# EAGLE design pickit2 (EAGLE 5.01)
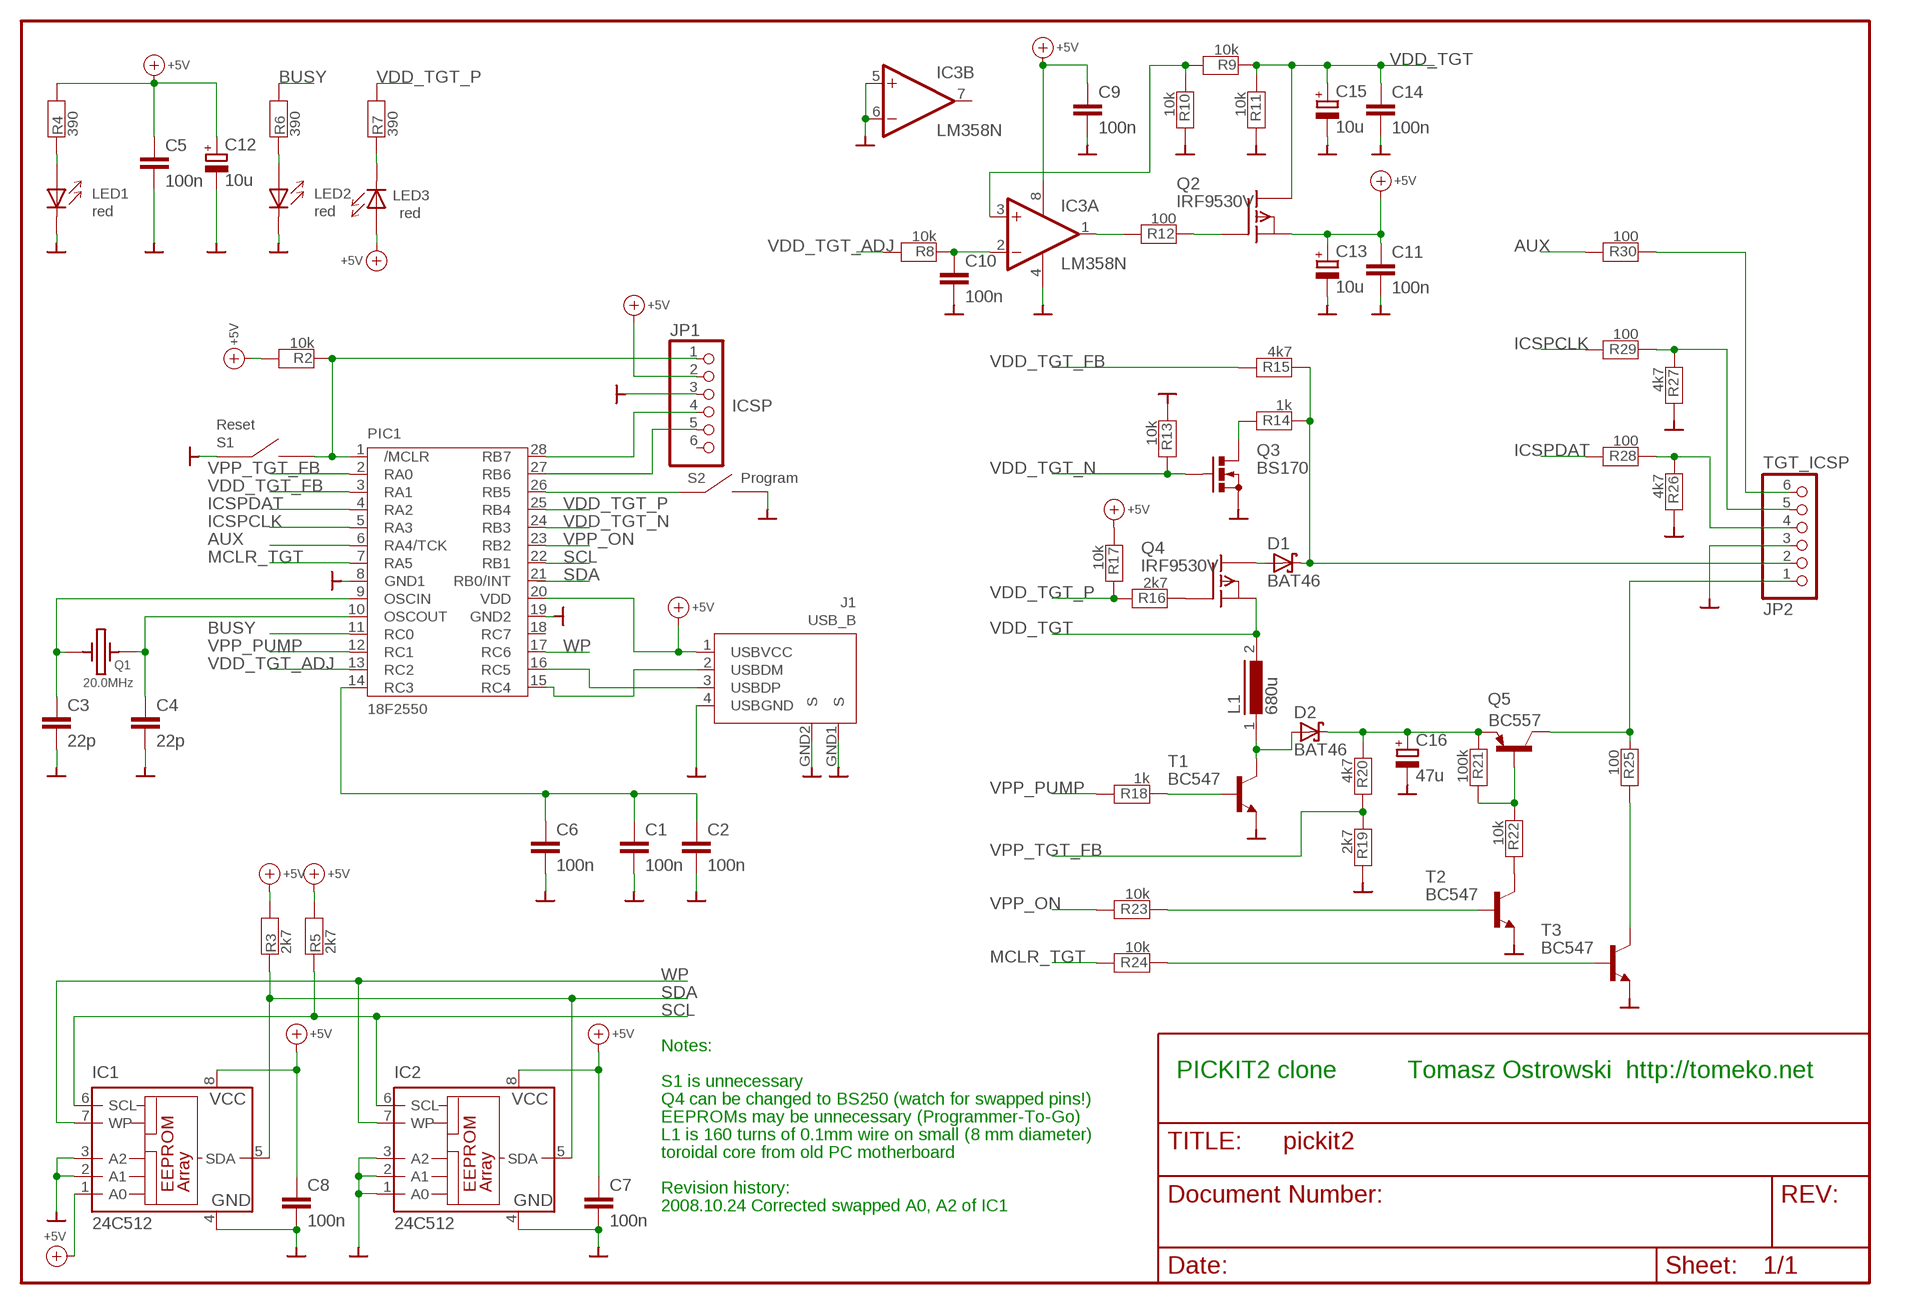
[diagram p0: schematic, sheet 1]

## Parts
C1  100n  C0805  [0805]
C2  100n  C0805  [0805]
C3  22p  C0805  [0805]
C4  22p  C0805  [0805]
C5  100n  C0805  [0805]
C6  100n  C0805  [0805]
C7  100n  C0805  [0805]
C8  100n  C0805  [0805]
C9  100n  C0805  [0805]
C10  100n  C0805  [0805]
C11  100n  C0805  [0805]
C12  10u  CPOL-EUE2,5-6E  [E2,5-6E]
C13  10u  CPOL-EUE2,5-6E  [E2,5-6E]
C14  100n  C0805  [0805]
C15  10u  CPOL-EUE2,5-6E  [E2,5-6E]
C16  47u  CPOL-EUE2,5-6E  [E2,5-6E]
D1  BAT46  BAT49  [DO41-10]
D2  BAT46  BAT49  [DO41-10]
IC1  24C512  24C04P  [DIL8]
IC2  24C512  24C04P  [DIL8]
IC3  LM358N  [DIL08]
J1  USB_B  [USB_B]
JP1  ICSP  PINHD-1X6  [1X06]
JP2  TGT_ICSP  PINHD-1X6  [1X06]
L1  680u  82114R  [82114R]
LED1  red  LED_5MM  [LED_5MM]
LED2  red  LED_5MM  [LED_5MM]
LED3  red  LED_5MM  [LED_5MM]
PIC1  18F2550  16C73  [DIL-28SB]
Q1  20.0MHz  QUARZ_STEH  [QUARZ_ST]
Q2  IRF9530V  [TO220V]
Q3  BS170  [SOT54E]
Q4  IRF9530V  [TO220V]
Q5  BC557  [TO92]
R2  10k  R_10MM  [RES04]
R3  2k7  R_10MM  [RES04]
R4  390  R_10MM@2  [RES04]
R5  2k7  R_10MM  [RES04]
R6  390  R_10MM@2  [RES04]
R7  390  R_10MM@2  [RES04]
R8  10k  R_10MM  [RES04]
R9  10k  R_10MM  [RES04]
R10  10k  R_10MM  [RES04]
R11  10k  R_10MM  [RES04]
R12  100  R_10MM  [RES04]
R13  10k  R_10MM  [RES04]
R14  1k  R_10MM  [RES04]
R15  4k7  R_10MM  [RES04]
R16  2k7  R_10MM  [RES04]
R17  10k  R_10MM  [RES04]
R18  1k  R_10MM  [RES04]
R19  2k7  R_10MM  [RES04]
R20  4k7  R_10MM  [RES04]
R21  100k  R_10MM  [RES04]
R22  10k  R_10MM  [RES04]
R23  10k  R_10MM  [RES04]
R24  10k  R_10MM  [RES04]
R25  100  R_10MM  [RES04]
R26  4k7  R_10MM  [RES04]
R27  4k7  R_10MM  [RES04]
R28  100  R_10MM  [RES04]
R29  100  R_10MM  [RES04]
R30  100  R_10MM  [RES04]
S1  Reset  MAUSTASTER  [MAUS]
S2  Program  MAUSTASTER  [MAUS]
T1  BC547  [TO92]
T2  BC547  [TO92]
T3  BC547  [TO92]

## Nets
+5V: C5.1 C7.1 C8.1 C9.1 C11.1 C12.+ C13.+ IC1.1(A0) IC1.8(VCC) IC2.8(VCC) IC3.8(P:V+) J1.1(USBVCC) JP1.2 LED3.A PIC1.20(VDD) Q2.3(S) R2.2 R3.2 R4.2 R5.2 R17.1
AUX: PIC1.6(RA4/TCK) R30.2
BUSY: PIC1.11(RC0) R6.2
GND: C1.2 C2.2 C3.2 C4.2 C5.2 C6.2 C7.2 C8.2 C9.2 C10.2 C11.2 C12.- C13.- C14.2 C15.- C16.- IC1.2(A1) IC1.3(A2) IC1.4(GND) IC2.1(A0) IC2.2(A1) IC2.3(A2) IC2.4(GND) IC3.4(P:V-) IC3.5(B:+IN) IC3.6(B:-IN) J1.4(USBGND) J1.GND1(S) J1.GND2(S) JP1.3 JP2.3 LED1.K LED2.K PIC1.8(GND1) PIC1.19(GND2) Q3.S R10.2 R11.2 R13.1 R19.2 R26.2 R27.2 S1.1 S1.1A S2.2 S2.2A T1.1(E) T2.1(E) T3.1(E)
ICSPCLK: PIC1.5(RA3) R29.2
ICSPDAT: PIC1.4(RA2) R28.2
J21: C1.1 C2.1 C6.1 PIC1.14(RC3)
MCLR_TGT: PIC1.7(RA5) R24.2
N$1: LED2.A R6.1
N$2: JP1.4 PIC1.28(RB7)
N$3: C3.1 PIC1.9(OSCIN) Q1.1
N$4: C4.1 PIC1.10(OSCOUT) Q1.2
N$5: JP1.5 PIC1.27(RB6)
N$6: LED3.K R7.1
N$7: LED1.A R4.1
N$8: J1.2(USBDM) PIC1.15(RC4)
N$9: J1.3(USBDP) PIC1.16(RC5)
N$10: PIC1.26(RB5) S2.1 S2.1A
N$11: C10.1 IC3.2(A:-IN) R8.1
N$12: IC3.3(A:+IN) R9.2 R10.1
N$14: Q3.D R14.2
N$15: D1.C JP2.2 R14.1 R15.1
N$16: JP1.1 PIC1.1(/MCLR) R2.1 S1.2 S1.2A
N$17: IC3.1(A:OUT) R12.2
N$18: Q2.1(G) R12.1
N$19: Q4.1(G) R16.1
N$20: D1.A Q4.2(D)
N$21: D2.A L1.1 T1.3(C)
N$22: R18.1 T1.2(B)
N$24: R24.1 T3.2(B)
N$25: C16.+ D2.C Q5.1(E) R20.1 R21.1
N$26: Q5.2(B) R21.2 R22.1
N$27: R22.2 T2.3(C)
N$28: R25.2 T3.3(C)
N$29: R23.1 T2.2(B)
N$30: JP2.1 Q5.3(C) R25.1
N$31: JP2.4 R26.1 R28.1
N$32: JP2.5 R27.1 R29.1
N$33: JP2.6 R30.1
SCL: IC1.6(SCL) IC2.6(SCL) PIC1.22(RB1) R5.1
SDA: IC1.5(SDA) IC2.5(SDA) PIC1.21(RB0/INT) R3.1
VDD_TGT: C14.1 C15.+ L1.2 Q2.2(D) Q4.3(S) R9.1 R11.1
VDD_TGT_ADJ: PIC1.13(RC2) R8.2
VDD_TGT_FB: PIC1.3(RA1) R15.2
VDD_TGT_N: PIC1.24(RB3) Q3.G R13.2
VDD_TGT_P: PIC1.25(RB4) R7.2 R16.2 R17.2
VPP_ON: PIC1.23(RB2) R23.2
VPP_PUMP: PIC1.12(RC1) R18.2
VPP_TGT_FB: PIC1.2(RA0) R19.1 R20.2
WP: IC1.7(WP) IC2.7(WP) PIC1.17(RC6)
Unconnected: IC3.7(B:OUT) JP1.6 PIC1.18(RC7)

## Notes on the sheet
- Notes:
- PICKIT2 clone | Tomasz Ostrowski  http://tomeko.net
- S1 is unnecessary
- Q4 can be changed to BS250 (watch for swapped pins!)
- EEPROMs may be unnecessary (Programmer-To-Go)
- L1 is 160 turns of 0.1mm wire on small (8 mm diameter)
- toroidal core from old PC motherboard
- Revision history:
- 2008.10.24 Corrected swapped A0, A2 of IC1

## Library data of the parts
C1-C11 C14 = capacitor-wima:C: CAPACITOR
C12 C13 C15 C16 = rcl:CPOL-EU: POLARIZED CAPACITOR, European symbol
D1 D2 = diode:BAT49: DIODE
IC1 IC2 = microchip:24C*: Serial EEPROM 1 K/2 K/4 K
IC3 = linear:LM358: OP AMP also LM158; LM258; LM2904 Source: http://cache.national.com/ds/LM/LM158.pdf
J1 = 8031bord:USB_B
JP1 JP2 = pinhead:PINHD-1X6: PIN HEADER
L1 = inductors:82114R: INDUCTOR
LED1-LED3 = holgnorm:LED_5MM
PIC1 = pic:16C73
Q1 = bts:QUARZ_STEH
Q2 Q4 = transistor-fet:IRF9530: P-Channel Enhancement MOSFET (HEXFET); -100V; -12A; 0,3Ohm
Q3 = transistor-small-signal:BS170: N-CHANNEL MOS FET
Q5 = transistor-pnp:BC557: PNP Transistor
R2 R3 R5 R8-R30 = holgnorm:R_10MM
R4 R6 R7 = holgnorm:R_10MM@2
S1 S2 = taster:MAUSTASTER
T1-T3 = transistor:BC547: NPN TRANSISTOR

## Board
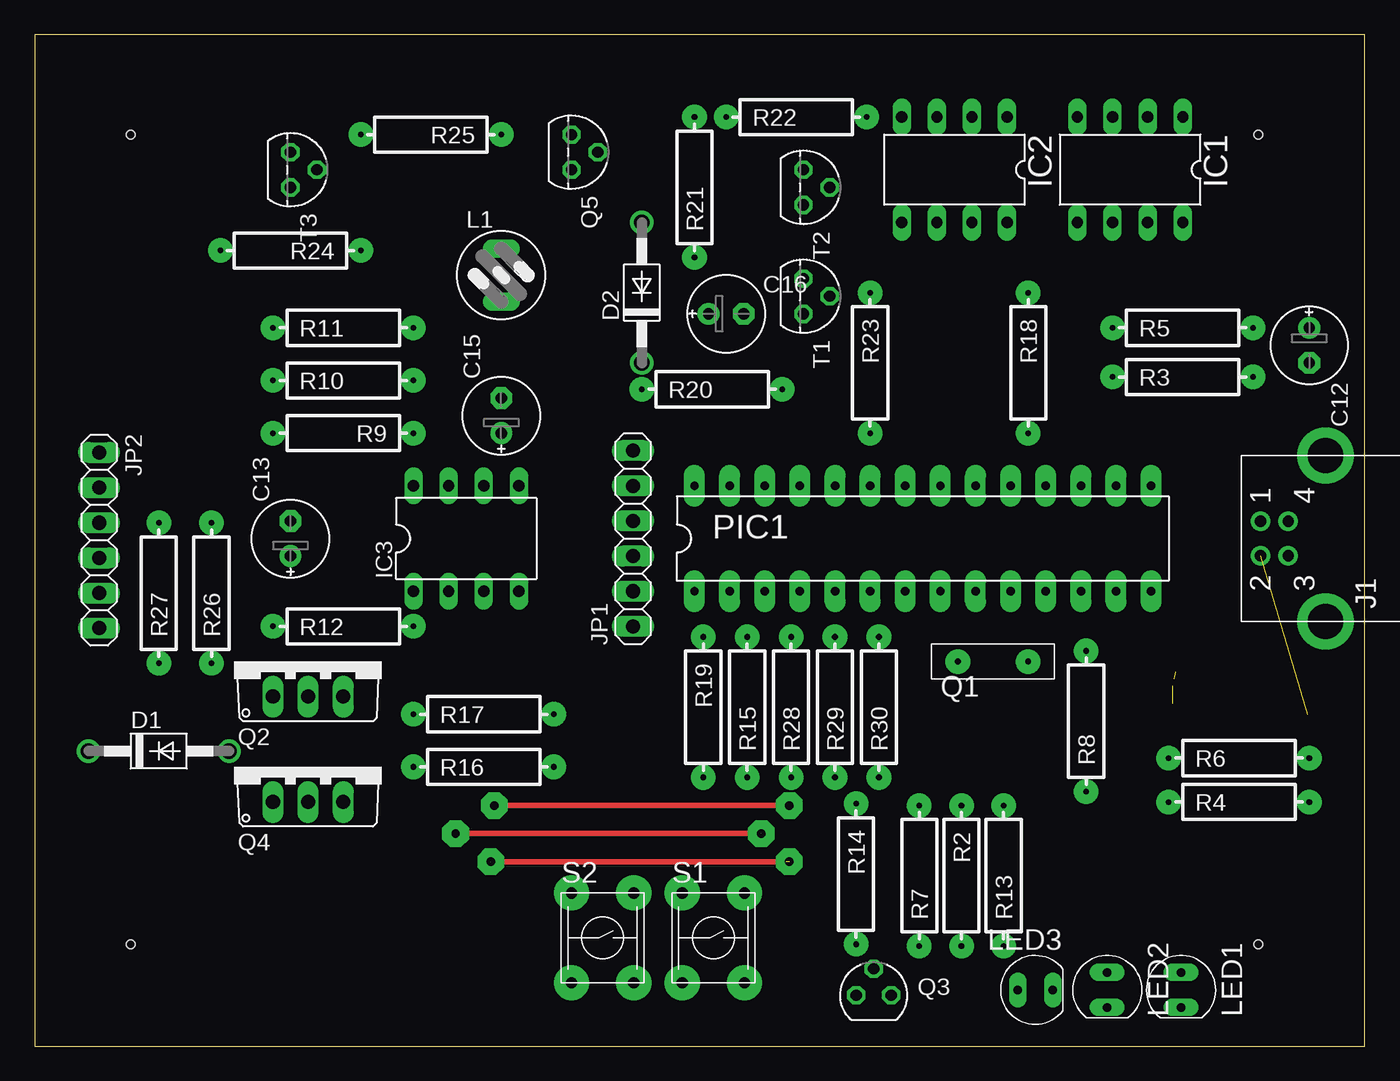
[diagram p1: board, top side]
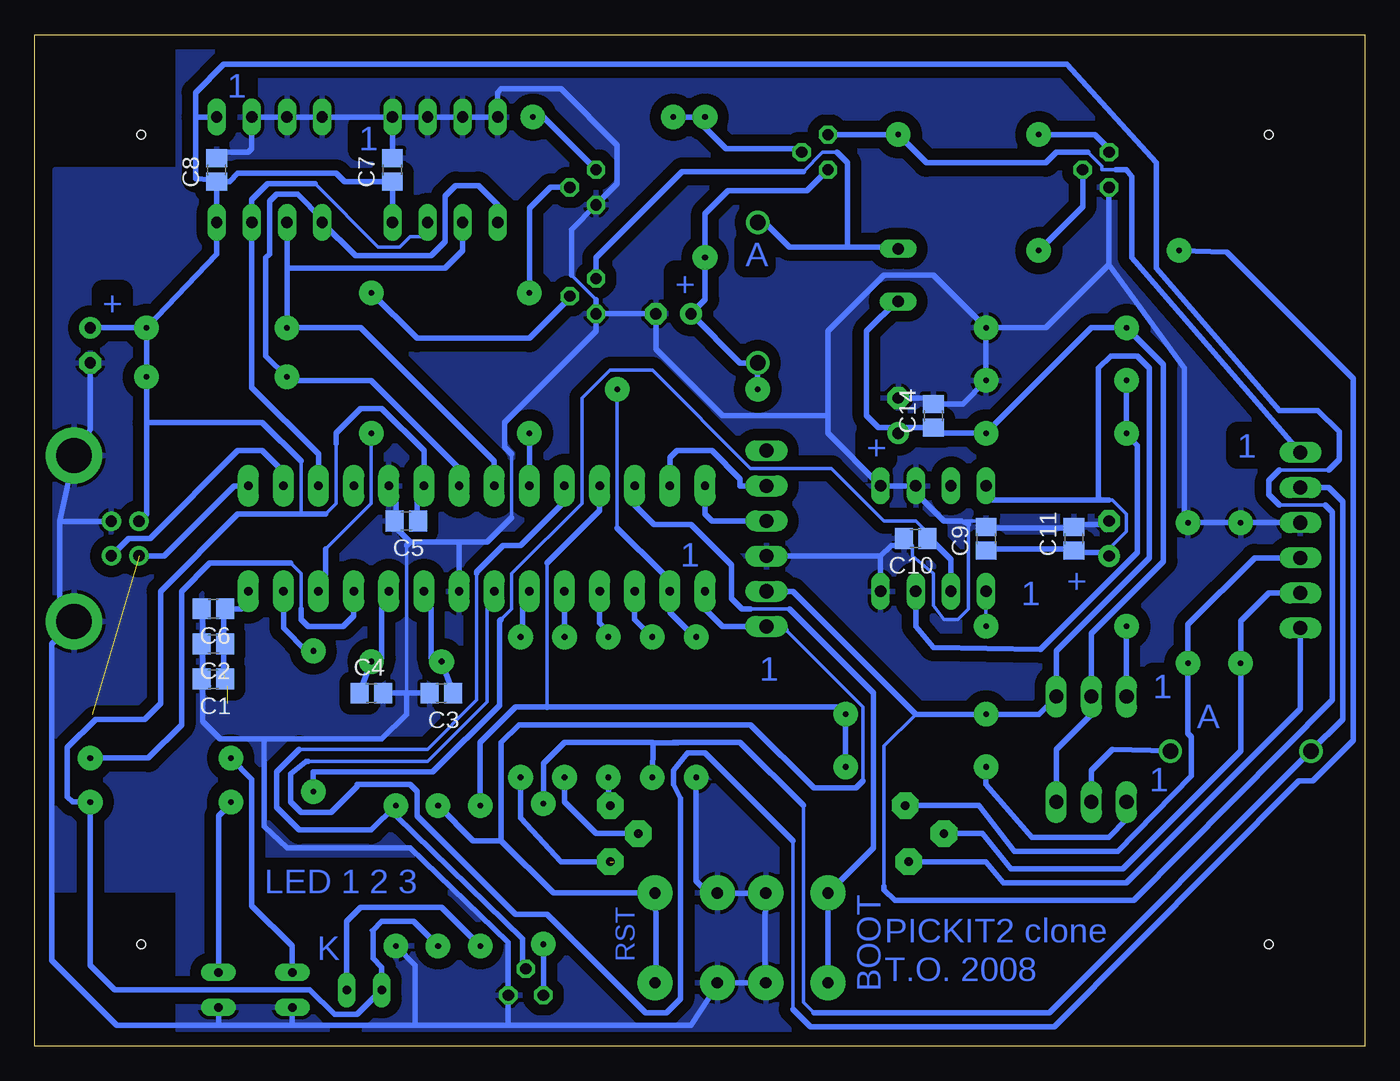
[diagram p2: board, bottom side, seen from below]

Size 96.19 x 73.14 mm. Coordinates in mm from the lower left corner, seen from the top.
Outline: 0,0 96.19,0 96.19,73.14 0,73.14 0,0
Copper layers (1*16): Top 0.035mm / dielectric 1.5mm / Bottom 0.035mm
Design rules "default *": minimum track width 10mil, minimum drill 24mil, track to track 12mil, track to pad 12mil, pad to pad 9mil, via to via 9mil, smd to smd 12mil, copper to edge 40mil, drill to drill 8mil, minimum pad ring 10mil, minimum via ring 8mil, stop-mask expansion 4mil, vias tented up to drill 0mil, thermal gap 10mil
Holes 0.6 mm at 6.95,7.36 6.95,65.91 88.48,65.91 88.48,7.36

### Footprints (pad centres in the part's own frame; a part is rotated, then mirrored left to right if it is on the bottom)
0805 = smd 1.3 x 1.5: 1 -0.85,0; 2 0.85,0
E2,5-6E = drill 0.813 pad 1.575 round: + -1.27,0 | drill 0.813 pad 1.575 octagon: - 1.27,0
DO41-10 = drill 1.118 round: A 5.08,0; C -5.08,0
DIL8 = drill 0.813 long: 1 -3.81,-3.81; 2 -1.27,-3.81; 3 1.27,-3.81; 4 3.81,-3.81; 5 3.81,3.81; 6 1.27,3.81; 7 -1.27,3.81; 8 -3.81,3.81
DIL08 = drill 0.813 long: 1 -3.81,-3.81; 2 -1.27,-3.81; 3 1.27,-3.81; 4 3.81,-3.81; 5 3.81,3.81; 6 1.27,3.81; 7 -1.27,3.81; 8 -3.81,3.81
USB_B = drill 0.813 pad 1.422 round: 1 1.25,2; 2 -1.25,2; 3 -1.25,0; 4 1.25,0 | drill 2.54 pad 4.064 round: GND1 6,-2.7; GND2 -6,-2.7
1X06 = drill 1.016 long: 1 -6.35,0; 2 -3.81,0; 3 -1.27,0; 4 1.27,0; 5 3.81,0; 6 6.35,0
82114R = drill 0.813 long: 1 0,1.905; 2 0,-1.905
LED_5MM = drill 0.61 pad 1.27 long: A -1.27,0; K 1.27,0
DIL-28SB = drill 0.61 pad 1.524 long: 1 0,0; 2 2.54,0; 3 5.08,0; 4 7.62,0; 5 10.16,0; 6 12.7,0; 7 15.24,0; 8 17.78,0; 9 20.32,0; 10 22.86,0; 11 25.4,0; 12 27.94,0; 13 30.48,0; 14 33.02,0; 15 33.02,7.62; 16 30.48,7.62; 17 27.94,7.62; 18 25.4,7.62; 19 22.86,7.62; 20 20.32,7.62; 21 17.78,7.62; 22 15.24,7.62; 23 12.7,7.62; 24 10.16,7.62; 25 7.62,7.62; 26 5.08,7.62; 27 2.54,7.62; 28 0,7.62
QUARZ_ST = drill 0.406 pad 1.778 round: 1 -2.54,0; 2 2.54,0
TO220V = drill 1.016 long: 1 -2.54,-2.54; 2 0,-2.54; 3 2.54,-2.54
SOT54E = drill 0.813 octagon: D -1.27,0; G 0,1.905; S 1.27,0
TO92 = drill 0.813 octagon: 1 1.27,0; 2 0,1.905; 3 -1.27,0
RES04 = drill 0.406 pad 1.778 round: 1 -5.08,0; 2 5.08,0
MAUS = drill 0.813 pad 2.54 round: 1 0,0; 1A 0,6.5; 2 4.5,0; 2A 4.5,6.5

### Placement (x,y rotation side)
C1  83.27,26.54 180 bottom
C2  83.27,29.08 180 bottom
C3  66.76,25.52 180 bottom
C4  71.84,25.52 0 bottom
C5  69.3,37.97 180 bottom
C6  83.27,31.62 180 bottom
C7  70.32,63.37 90 bottom
C8  83.02,63.37 90 bottom
C9  27.39,36.7 90 bottom
C10  32.47,36.7 180 bottom
C11  21.04,36.7 90 bottom
C12  92.16,50.67 270 top
C13  18.5,36.7 90 top
C14  31.2,45.59 90 bottom
C15  33.74,45.59 90 top
C16  50,52.95 0 top
D1  8.98,21.33 0 top
D2  43.9,54.48 90 top
IC1  79.21,63.37 180 top
IC2  66.51,63.37 180 top
IC3  31.2,36.7 0 top
J1  90.64,36.7 90 top
JP1  43.27,36.7 90 top
JP2  4.66,36.57 270 top
L1  33.74,55.75 0 top
LED1  82.89,4.06 270 top
LED2  77.56,4.06 270 top
LED3  72.35,4.06 0 top
PIC1  47.71,32.89 0 top
Q1  69.3,27.81 0 top
Q2  19.77,27.81 0 top
Q3  60.67,3.68 0 top
Q4  19.77,20.19 0 top
Q5  38.82,64.64 270 top
R2  67.02,12.31 270 top
R3  83.02,48.38 0 top
R4  87.08,17.65 0 top
R5  83.02,51.94 0 top
R6  87.08,20.82 0 top
R7  63.97,12.31 90 top
R8  76.03,23.49 90 top
R9  22.31,44.32 180 top
R10  22.31,48.13 0 top
R11  22.31,51.94 0 top
R12  22.31,30.35 0 top
R13  70.07,12.31 90 top
R14  59.4,12.44 270 top
R15  51.52,24.51 90 top
R16  32.47,20.19 0 top
R17  32.47,24 0 top
R18  71.84,49.4 270 top
R19  48.35,24.51 270 top
R20  48.98,47.49 0 top
R21  47.71,62.1 90 top
R22  55.08,67.18 0 top
R23  60.41,49.4 270 top
R24  18.5,57.53 180 top
R25  28.66,65.91 180 top
R26  12.79,32.76 90 top
R27  8.98,32.76 90 top
R28  54.7,24.51 90 top
R29  57.87,24.51 90 top
R30  61.05,24.51 90 top
S1  46.83,4.57 0 top
S2  38.82,4.57 0 top
T1  55.59,54.22 270 top
T2  55.59,62.1 270 top
T3  18.5,63.37 270 top

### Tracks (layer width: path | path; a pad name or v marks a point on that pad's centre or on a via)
+5V
  Bottom 0.254: 20.54,35.68 C11.1 21.55,35.94 | 26.89,35.94 C9.1 | 18.5,39.49 18.25,39.49 17.23,38.48 17.23,37.21 18.25,36.19 C13.+ | 68.54,38.48 C5.1 | 74.38,43.56 74.38,39.24 75.15,38.48 | 34.76,11.55 34.76,21.71 32.47,24 | 2.38,25.01 2.38,24.89 | 2.88,39.11 6.18,39.11 | 6.18,41.65 2.63,41.65 | C8.1 83.53,62.61 | 76.92,42.29 76.92,38.48 | 71.72,8.38 71.84,8.38
  Bottom 0.406: 20.54,35.68 19.27,35.68 C13.+ | 21.55,35.94 26.89,35.94 | 19.14,39.49 18.5,39.49 | 19.14,39.49 26.89,39.49 IC3.8 | C8.1 IC1.8 83.02,57.27 R5.2 | R5.2 C12.+ | 68.54,38.48 68.54,39.24 PIC1.20 68.03,43.05 71.08,46.1 72.61,46.1 74.38,44.32 74.38,43.56 | IC2.8 C7.1 73.79,62.52 74.38,63.11 81.5,63.11 82.09,62.52 C8.1 | 2.88,39.11 2.38,38.6 2.38,25.01 16.73,10.54 34,10.54 34.76,11.3 34.76,11.55 | 6.18,39.11 6.95,39.87 6.95,40.89 6.18,41.65 | 2.63,41.65 1.87,42.41 1.87,44.45 3.39,45.97 6.18,45.97 15.08,56.26 15.08,63.88 21.55,70.99 82.51,70.99 84.54,68.96 84.54,67.18 | R5.2 R3.2 88.1,45.08 | 88.1,45.08 88.1,38.48 88.63,37.95 J1.1 | 75.15,38.48 76.92,38.48 81.5,38.48 87.08,32.89 87.08,24.76 88.23,23.62 91.78,23.62 93.81,21.58 93.81,18.03 93.43,17.65 R4.2 92.16,5.84 90.39,4.06 76.29,4.06 74.51,2.28 72.86,2.28 LED3.A 70.95,4.06 71.08,4.19 71.08,5.71 71.72,6.34 71.72,8.38 71.08,9.01 68.8,9.01 R2.2 | 76.92,42.29 79.72,45.08 88.1,45.08 | 84.54,67.18 84.54,62.73 83.02,62.61 C8.1 | JP1.2 41.36,32.89 32.47,24 27.65,24 27.39,23.74 R17.1 23.58,24 Q2.3 22.31,28.57 15.58,35.3 15.58,49.02 16.47,49.91 18.38,49.91 19.27,49.02 19.27,39.62 19.14,39.49 | 84.54,67.18 IC1.1
AUX
  Bottom 0.254: R30.2 60.92,29.59
  Bottom 0.406: PIC1.6 60.92,31.62 60.92,29.59
BUSY
  Bottom 0.254: 76.92,31.62 76.92,34.16 77.69,34.92
  Bottom 0.406: 77.69,34.92 83.53,34.92 85.56,32.89 85.56,23.24 87.97,20.82 92.04,20.82 92.16,20.7 R6.2 | PIC1.11 73.11,31.11 73.88,30.35 76.42,30.35 76.92,30.86 76.92,31.62
GND
  Bottom 0.254: C1.2 84.04,27.05 | 84.04,28.57 C2.2 84.04,29.59 | 84.04,31.11 C6.2 | C4.2 71.08,25.52 | 70.07,38.48 C5.2 70.07,37.46 | 33.74,36.19 C10.2 32.73,36.19 32.73,35.43 31.2,34.16 31.2,31.87 30.44,30.86 29.43,30.86 28.66,31.62 28.66,37.71 28.92,37.97 27.9,37.97 C9.2 26.89,37.46 | 20.54,37.71 C11.2 21.55,37.46 | C1.2 83.53,26.03 | 55.59,53.97 57.37,55.75 | 65.49,67.18 IC2.3 | 61.68,42.79 61.68,38.22 | 69.3,36.19 69.3,25.52 | 84.04,26.54 C1.2 | 46.83,4.44 S1.1
  Bottom 0.406: C12.- 92.16,44.57 J1.GND1 94.36,37.97 | JP2.3 R27.2 R26.2 13.04,38.6 13.04,49.02 18.5,56.51 | 84.04,27.05 84.04,28.57 | 84.04,29.59 84.04,31.11 | 69.3,25.52 C4.2 | 69.3,25.52 C3.2 | 70.07,38.48 70.07,39.24 PIC1.19 | 69.05,36.44 70.07,37.46 | 20.54,37.71 19.27,37.71 C13.- | 26.89,37.46 21.55,37.46 | IC2.1 C7.2 | IC2.1 IC2.2 65.49,67.18 IC2.4 62.7,68.96 62.45,69.21 58.13,69.21 54.06,65.15 54.06,62.35 T2.1 57.37,59.05 57.37,55.75 | IC2.1 IC1.4 78.19,67.18 | S1.1 S2.2 43.4,4.95 43.4,9.27 S2.2A 44.41,11.04 45.68,11.04 S1.1A 47.48,11.07 48.35,11.93 R19.2 | 69.3,25.52 69.3,24 71.08,22.22 79.59,22.22 | T1.1 55.59,53.97 | T1.1 55.59,51.68 62.19,45.08 62.19,43.3 61.68,42.79 | 61.68,38.22 63.46,36.44 65.49,36.44 | 65.49,36.44 69.05,36.44 | T1.1 C16.- 51.27,50.41 46.44,45.59 38.82,45.59 | 69.05,36.44 69.3,36.19 | 65.49,36.44 PIC1.8 | 79.59,22.22 82.77,22.22 84.04,23.49 84.04,26.54 | 68.67,1.52 77.56,1.52 | 77.56,1.52 82.89,1.52 | 79.59,22.22 79.59,15.87 77.94,14.35 69.05,14.35 61.94,7.49 Q3.S | 61.94,1.52 48.73,1.52 46.83,4.44 | 61.94,1.52 68.67,1.52 | R11.2 23.08,51.94 18.5,56.51 | 18.5,56.51 T3.1 | C15.- 31.71,46.86 31.2,46.35 C14.2 29.08,46.44 R10.2 R11.2 | R11.2 31.2,55.75 34.76,55.75 38.82,51.68 38.82,45.59 | 38.82,45.59 38.82,44.32 IC3.5 IC3.6 32.47,40 30.44,37.97 29.17,37.97 28.66,37.71 | 33.74,36.19 34.25,36.19 35.01,35.43 | 35.01,35.43 IC3.4 | 35.01,35.43 JP1.3 | 94.36,37.97 94.36,30.89 94.32,30.86 94.45,30.73 93.37,30.73 J1.GND2 94.96,29.08 94.96,6.22 90.26,1.52 82.89,1.52 | 94.36,37.97 94.32,37.97 94.3,37.95 J1.4 | 77.56,1.52 LED2.K | 82.89,1.52 LED1.K | Q3.S 62.19,3.93 | Q3.S 61.94,1.52 | R13.1 68.67,5.84 68.67,1.52
  Bottom 0.406: IC1.2 80.73,67.18 | 78.19,67.18 IC1.2 | IC1.2 80.48,64.89 80.73,64.64 83.27,64.64 83.27,64.47 C8.2 | 78.19,67.18 IC1.3
  pour Bottom (isolate 0.813): 9.61,63.37 9.61,72.26 85.81,72.26 85.81,63.37 94.7,63.37 94.7,11.3 85.81,11.3 85.81,1.14 9.61,1.14 9.61,11.3 0.72,11.3 0.72,63.37
ICSPCLK
  Bottom 0.406: R29.2 PIC1.5
ICSPDAT
  Bottom 0.254: R28.2 54.7,29.97
  Bottom 0.406: 54.7,29.97 55.33,30.6 PIC1.4
J21  (2 unrouted)
  Bottom 0.254: 82.51,29.59 C2.1 82.51,28.57 | 82.51,31.11 C6.1 | 82.26,26.03 C1.1
  Bottom 0.406: 82.51,29.59 82.51,31.11 | C6.1 81.24,31.62 PIC1.14 | 82.51,28.57 82.51,27.05
MCLR_TGT
  Bottom 0.254: 76.42,20.57 67.78,20.57 63.46,24.89 63.46,31.62 PIC1.7 | 41.36,2.66 41.36,14.85
  Bottom 0.406: 41.36,14.85 47.71,21.2 48.98,21.2 50,19.93 50,18.92 49.49,17.9 49.49,3.42 50.51,2.41 52.03,2.41 59.14,9.52 61.43,9.52 68.54,16.63 68.54,18.41 69.05,18.92 72.86,18.92 72.86,18.79 74.77,16.89 76.92,16.89 77.69,17.65 77.69,19.68 76.54,20.57 76.42,20.57 | R24.2 10,57.4 0.85,48.25 0.85,22.09 3.77,19.17 4.79,19.17 22.44,1.39 40.09,1.39 41.36,2.66
N$1
  Bottom 0.406: R6.1 80.48,19.3 80.48,10.16 77.56,7.23 LED2.A
N$2
  Bottom 0.406: JP1.4 47.21,37.97 47.71,38.48 PIC1.28
N$3
  Bottom 0.406: C3.1 Q1.1 67.53,28.06 67.53,31.62 PIC1.9
N$4
  Bottom 0.406: C4.1 Q1.2 71.08,28.06 71.08,31.62 PIC1.10
N$5
  Bottom 0.406: JP1.5 45.17,40.51 45.17,41.02 47.21,43.05 49.75,43.05 50.25,42.54 PIC1.27
N$6
  Bottom 0.406: R7.1 66.76,10.03 72.61,10.03 73.62,9.01 LED3.K
N$7
  Bottom 0.406: R4.1 82,17.52 82.89,16.63 LED1.A
N$8  (1 unrouted)
  Bottom 0.406: PIC1.15 81.75,40.51 86.83,35.43 88.61,35.43 | 88.61,35.43 88.63,35.45 J1.2 88.59,35.45 88.61,35.43
N$9
  Bottom 0.406: PIC1.16 78.19,41.52 79.72,43.05 81.5,43.05 87.85,36.7 89.37,36.7 90.64,35.43 J1.3
N$10
  Bottom 0.254: 41.62,31.62 44.41,31.62
  Bottom 0.406: 41.62,31.62 35.52,25.52 35.52,14.35 38.32,11.55 S2.1A S2.1 | 44.41,31.62 45.05,31.62 45.81,32.38 45.81,34.79 48.73,37.71 51.4,37.71 52.79,39.11 PIC1.26
N$11
  Bottom 0.254: 62.45,30.86 61.68,31.62 61.68,34.16 56.6,39.24 56.6,46.86 54.57,48.89 51.52,48.89 44.41,41.78 38.57,41.78 34.76,37.97 32.47,37.97 31.71,37.21 C10.1
  Bottom 0.406: C10.1 31.46,36.7 29.93,35.17 IC3.2 | 62.45,30.86 62.57,30.73 62.57,24.63 67.4,19.81 76.03,19.81 R8.1
N$12
  Bottom 0.406: R10.1 R9.2 17.23,44.19 16.47,43.43 16.47,35.68 23.46,28.7 31.2,28.82 32.47,30.35 IC3.3
N$13  (via drill 0.6 pad 1.93)
  other vias: 52.54,15.36
N$14
  Bottom 0.254: Q3.D 59.14,3.68 59.4,3.93
  Bottom 0.406: 59.4,3.93 R14.2
N$15
  Bottom 0.254: 50,21.97 51.48,21.93 51.49,21.93 51.52,21.97 | 40.6,17.39 40.6,3.17 39.84,2.41 | 49.71,21.93 49.75,21.97
  Bottom 0.406: 50,21.97 45.17,21.97 40.6,17.39 | R15.1 51.48,21.93 49.71,21.93 | R14.1 59.4,20.44 57.87,21.97 51.52,21.97 | 39.84,2.41 22.82,2.41 D1.C 1.61,23.62 1.61,39.37 2.63,40.38 JP2.2
N$16
  Bottom 0.254: 41.87,30.09 36.28,24.51 36.28,19.17
  Bottom 0.406: 36.28,19.17 36.79,18.66 39.84,18.66 44.41,23.24 61.18,23.24 62.45,21.97 62.45,14.85 | 41.87,30.09 JP1.1 46.44,30.35 47.71,31.62 PIC1.1 | S1.2 51.27,4.95 51.27,9.27 S1.2A 58.66,11.07 62.45,14.85 | 62.45,14.85 64.48,14.85 R2.1
N$17
  Bottom 0.254: R12.2 IC3.1
N$18
  Bottom 0.406: Q2.1 R12.1
N$19
  Bottom 0.406: Q4.1 17.23,16.38 18.5,15.11 24.09,15.11 27.39,18.92 R16.1
N$20
  Bottom 0.406: D1.A 18.25,21.46 19.77,19.93 Q4.2
N$21
  Bottom 0.254: 40.6,63.24 39.2,64.64 38.19,64.64
  Bottom 0.406: 37.43,57.78 41.62,57.78 43.14,59.3 D2.A | 37.43,57.78 35.01,57.78 L1.1 | 38.19,64.64 37.43,63.88 37.43,57.78 | 40.6,63.24 49.37,63.24 55.59,57.02 T1.3
N$22
  Bottom 0.254: T1.2 57.49,54.1
  Bottom 0.406: 57.49,54.1 60.41,51.18 68.54,51.18 R18.1
N$23  (via drill 0.6 pad 1.93)
  other vias: 32.98,13.33
N$24
  Bottom 0.406: T3.2 20.41,60.7 R24.1
N$25
  Bottom 0.254: R21.1 47.71,58.03
  Bottom 0.406: R20.1 D2.C 45.17,49.4 C16.+ 47.71,53.97 R21.1 47.71,60.19 46.06,61.84 40.35,61.84 Q5.1
N$26
  Bottom 0.406: Q5.2 41.36,64.89 46.19,64.89 48.22,66.92 R21.2 R22.1
N$27
  Bottom 0.406: R22.2 59.4,67.18 T2.3
N$28
  Bottom 0.406: T3.3 18.5,64.89 19.52,65.91 R25.2 23.84,65.91
N$29
  Bottom 0.406: T2.2 58.89,62.1 60.41,60.57 R23.1
N$30
  Bottom 0.254: 18,63.37 19.01,63.37 19.01,63.62 20.03,64.64
  Bottom 0.406: Q5.3 R25.1 31.71,63.88 23.08,63.88 22.31,64.64 20.03,64.64 | JP2.1 16.85,57.02 16.85,62.86 17.23,63.37 18,63.37
N$31  (via drill 0.6 pad 1.93)
  Top 0.254: v33.24,17.39 v54.57,17.39 | v33.24,17.39 v54.57,17.39 | v33.24,17.39 v54.57,17.39
  Top 0.406: v33.24,17.39 v54.57,17.39
  Bottom 0.254: v54.57,17.39 54.7,17.52
  Bottom 0.406: v33.24,17.39 27.9,17.39 25.36,14.09 17.87,14.09 12.54,19.55 12.54,22.35 12.79,22.6 R26.1 12.79,30.47 7.96,35.3 JP2.4 | 54.7,17.52 R28.1
N$32  (via drill 0.6 pad 1.93)  (1 unrouted)
  Top 0.406: v30.44,15.36 52.54,15.36
  Bottom 0.406: v30.44,15.36 27.65,15.36 25.62,12.82 17.49,12.82 8.98,21.33 8.98,27.81 | R29.1 57.87,17.65 55.59,15.36 52.54,15.36 | JP2.5 6.95,32.76 8.98,30.73 8.98,27.81 | 8.98,27.81 R27.1
N$33  (2 unrouted)
  Top 0.406: 32.98,13.33 54.57,13.33
  Bottom 0.406: JP2.6 4.66,24.38 17.23,11.81 26.12,11.81 27.39,13.33 32.98,13.33 | R30.1 61.05,16.5 58.13,13.33 54.32,13.33
N$34  (via drill 0.6 pad 1.93)
  other vias: 54.57,13.33
SCL
  Bottom 0.406: PIC1.22 62.95,42.29 72.61,51.94 R5.1 77.94,56.26 | 77.94,56.26 IC1.6 | IC2.6 65.24,57.53 66.51,56.26 77.94,56.26
SDA
  Bottom 0.254: R3.1 78.19,47.87 77.94,48.13
  Bottom 0.406: PIC1.21 65.49,41.78 71.84,48.13 77.94,48.13 | R3.1 79.46,49.91 79.46,57.02 79.21,57.27 79.21,61.08 78.7,61.59 77.18,61.59 75.4,59.81 IC1.5 72.99,57.14 67.53,57.14 66.51,58.16 66.51,61.46 65.75,62.23 64.1,62.23 62.7,60.83 IC2.5
VDD_TGT
  Bottom 0.254: 31.71,44.57 C14.1 30.7,44.32
  Bottom 0.406: C15.+ 33.49,44.32 33.07,44.74 | 33.07,44.74 C14.1 31.2,44.57 30.95,44.32 R9.1 19.77,51.94 R11.1 14.57,49.27 14.57,35.05 19.77,29.84 Q2.2 19.77,24 22.31,21.46 Q4.3 | 33.07,44.74 35.18,44.74 36.03,45.59 36.03,51.68 33.74,53.97 L1.2
VDD_TGT_ADJ
  Bottom 0.406: R8.2 76.54,28.57 78.19,30.22 PIC1.13
VDD_TGT_FB
  Bottom 0.406: R15.2 52.79,30.86 PIC1.3
VDD_TGT_N
  Bottom 0.254: 64.22,34.16 64.22,25.01 67.78,21.46 77.05,21.46
  Bottom 0.406: 77.05,21.46 78.7,19.81 78.7,17.27 77.05,15.62 71.84,15.62 R13.2 70.07,16.63 60.92,7.74 60.92,6.22 60.67,5.71 Q3.G | 64.22,34.16 64.22,34.28 62.32,36.19 61.05,36.19 57.87,39.37 PIC1.24
VDD_TGT_P
  Bottom 0.254: 59.14,24.51 | 59.14,24.51 59.14,34.92
  Bottom 0.406: R16.2 R17.2 38.06,24.51 59.14,24.51 | R7.2 63.97,21.97 61.43,24.51 59.14,24.51 | 59.14,24.51 59.14,24.48 | PIC1.25 55.33,38.73 59.14,34.92
VPP_ON
  Bottom 0.406: PIC1.23 R23.2
VPP_PUMP
  Bottom 0.254: 75.15,35.94 71.84,39.24 R18.2
  Bottom 0.406: 75.15,35.94 75.15,34.16 PIC1.12
VPP_TGT_FB
  Bottom 0.254: 54.06,37.46 R20.2 | R19.1 48.48,29.59
  Bottom 0.406: 54.06,37.46 50.76,34.16 PIC1.2 50.25,31.36 48.48,29.59
WP
  Bottom 0.254: IC2.7 68.29,58.54 69.05,58.54 69.81,57.78 71.34,57.78 75.91,62.35
  Bottom 0.406: PIC1.17 75.65,42.79 80.48,47.62 IC1.7 80.48,61.21 79.34,62.35 75.91,62.35

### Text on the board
Bottom: 1 | 1 | A | + | + | 1 | + | 1 | + | 1 | 1 | 1 | A | 1 | LED 1 2 3 | PICKIT2 clone | K | RST | T.O. 2008 | BOOT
